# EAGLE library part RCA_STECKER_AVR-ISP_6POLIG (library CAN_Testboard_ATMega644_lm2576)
ISP (In System Programming) Stecker fr AVRs ber diesen Anschlu kann ein AVR mit einem Standard ISP-Kabel direkt an einen Parallelport des PCs angeschlossen und programmiert werden.
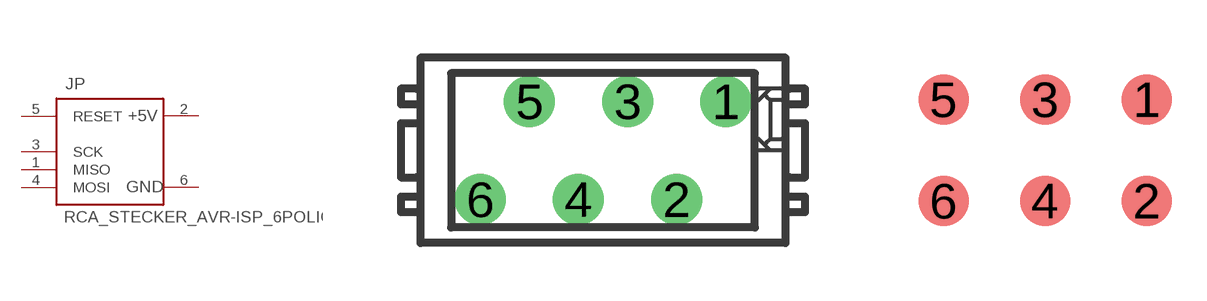
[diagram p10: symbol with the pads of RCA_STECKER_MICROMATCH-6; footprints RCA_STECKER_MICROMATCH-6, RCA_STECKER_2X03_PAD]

Designator prefix JP

## RCA_STECKER_AVR-ISP_6POLIGM  [RCA_STECKER_MICROMATCH-6]
1  MISO
2  +5V  pwr
3  SCK  in
4  MOSI
5  RESET  in
6  GND  pwr

## RCA_STECKER_AVR-ISP_6POLIGP  [RCA_STECKER_2X03_PAD]
Pads as for RCA_STECKER_MICROMATCH-6

## RCA_STECKER_AVR-ISP_6POLIGS  [RCA_STECKER_2X03]
Pads as for RCA_STECKER_MICROMATCH-6

## RCA_STECKER_AVR-ISP_6POLIGSV  [RCA_STECKER_2X03/90]
Pads as for RCA_STECKER_MICROMATCH-6

## RCA_STECKER_AVR-ISP_6POLIGW  [RCA_STECKER_ML6]
Pads as for RCA_STECKER_MICROMATCH-6

## RCA_STECKER_AVR-ISP_6POLIGWV  [RCA_STECKER_ML6L]
Pads as for RCA_STECKER_MICROMATCH-6

## Footprint RCA_STECKER_MICROMATCH-6 (pad centres in mm)
MicroMaTch 6 7-215464-6 / 0-215464-6 Drawing Number C-215464 DDEController.pdf
drill 0.813 round: 1 3.175,1.27; 2 1.905,-1.27; 3 0.635,1.27; 4 -0.635,-1.27; 5 -1.905,1.27; 6 -3.175,-1.27

## Footprint RCA_STECKER_2X03_PAD (pad centres in mm)
SMD Augen zum Aufdrcken einer zweireihigen Stiftleiste.
smd 1.27 x 1.27: 1 2.54,1.27; 2 2.54,-1.27; 3 0,1.27; 4 0,-1.27; 5 -2.54,1.27; 6 -2.54,-1.27

## Footprint RCA_STECKER_2X03 (pad centres in mm)
PIN HEADER
drill 1.016 octagon: 1 -2.54,-1.27; 2 -2.54,1.27; 3 0,-1.27; 4 0,1.27; 5 2.54,-1.27; 6 2.54,1.27

## Footprint RCA_STECKER_2X03/90 (pad centres in mm)
PIN HEADER
drill 1.016 octagon: 1 -2.54,-1.27; 2 -2.54,1.27; 3 0,-1.27; 4 0,1.27; 5 2.54,-1.27; 6 2.54,1.27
